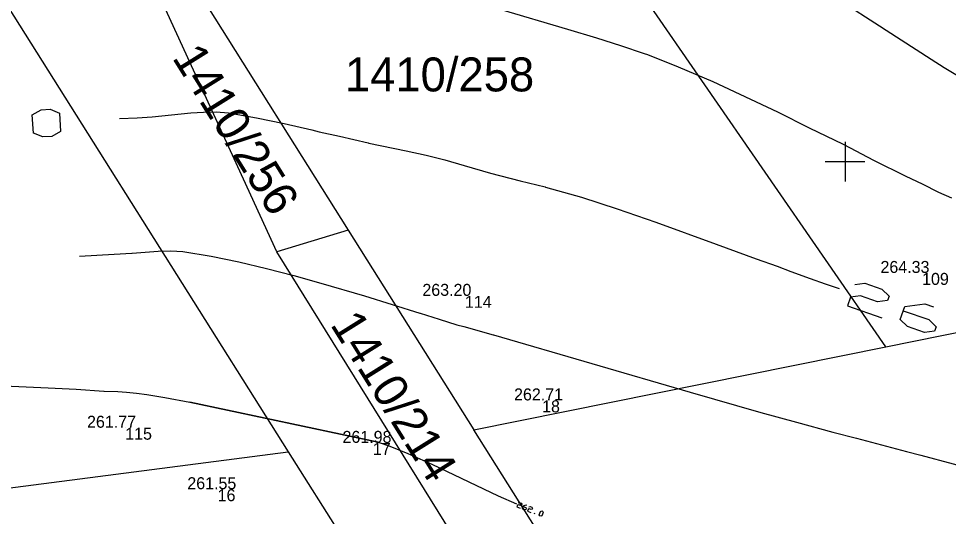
# Model space of a CAD drawing. Extents: x -771260 to -770828, y -1053564 to -1052811.
# Drawn here: x -771091.4 to -771044.82, y -1053317.78 to -1053292.83 of the extents above; entities that cross this region are included whole.
import ezdxf

# ---------------------------------------------------------------- set-up
doc = ezdxf.new("R2010")
doc.units = 0
for name, color, linetype in [('14_8_2023_krizky', 7, 'Continuous'), ('22_4_2022_vrstevnice_interval_po1m', 7, 'Continuous'), ('22_4_2022_zamereny_bod', 7, 'Continuous'), ('22_4_2022_zamereny_bod_cislo', 7, 'Continuous'), ('22_4_2022_zamereny_bod_vyska', 7, 'Continuous'), ('25_3_2019_krizky_JTSK', 7, 'Continuous'), ('25_3_2019_vrstevnice_interval_po_1m', 7, 'Continuous'), ('25_3_2019_zamereny_bod', 7, 'Continuous'), ('25_3_2019_zamereny_bod_cislo', 7, 'Continuous'), ('25_3_2019_zamereny_bod_vyska', 7, 'Continuous'), ('Default', 7, 'Continuous'), ('DKM_Hranice parcel', 7, 'Continuous'), ('DKM_Parcelní čísla', 7, 'Continuous')]:
    doc.layers.add(name, color=color, linetype=linetype)

# ---------------------------------------------------------------- blocks, each defined once
blk = doc.blocks.new('POINT_DISPLAY')
at = {"layer": 'Default'}
blk.add_line((0, 0), (0, 0), dxfattribs=at)
blk = doc.blocks.new('KRIZEK')
at = {"layer": '25_3_2019_krizky_JTSK'}
for p, q in [((0, 10), (0, -10)), ((-10, 0), (10, 0))]:
    blk.add_line(p, q, dxfattribs=at)

msp = doc.modelspace()

# ---------------------------------------------------------------- linework, layer by layer
at = {"layer": '22_4_2022_vrstevnice_interval_po1m'}
for points in [[(-771073.389, -1053314.051), (-771082.816, -1053312.053), (-771073.389, -1053314.051)], [(-771073.389, -1053314.051), (-771072.797, -1053314.255), (-771071.898, -1053314.616), (-771070.701, -1053315.152), (-771067.369, -1053316.747), (-771066.465, -1053317.153)], [(-771072.797, -1053314.255), (-771072.797, -1053314.255)], [(-771071.898, -1053314.616), (-771071.898, -1053314.616)], [(-771070.701, -1053315.152), (-771070.701, -1053315.152)], [(-771067.369, -1053316.747), (-771067.369, -1053316.747)], [(-771066.367, -1053317.098), (-771066.307, -1053317.075), (-771066.218, -1053317.109), (-771066.189, -1053317.167), (-771066.205, -1053317.207), (-771066.265, -1053317.23), (-771066.354, -1053317.196), (-771066.414, -1053317.219), (-771066.445, -1053317.3), (-771066.267, -1053317.369)], [(-771066.132, -1053317.282), (-771065.998, -1053317.334), (-771065.969, -1053317.391), (-771065.985, -1053317.432), (-771066.045, -1053317.455), (-771066.134, -1053317.42), (-771066.163, -1053317.363), (-771066.116, -1053317.242), (-771065.996, -1053317.195), (-771065.951, -1053317.212)], [(-771065.834, -1053317.304), (-771065.774, -1053317.281), (-771065.685, -1053317.316), (-771065.656, -1053317.373), (-771065.671, -1053317.414), (-771065.731, -1053317.437), (-771065.82, -1053317.402), (-771065.881, -1053317.426), (-771065.912, -1053317.506), (-771065.734, -1053317.575)], [(-771065.556, -1053317.644), (-771065.54, -1053317.604)], [(-771065.289, -1053317.747), (-771065.318, -1053317.69), (-771065.256, -1053317.528), (-771065.196, -1053317.505), (-771065.151, -1053317.522), (-771065.122, -1053317.579), (-771065.185, -1053317.741), (-771065.245, -1053317.764), (-771065.289, -1053317.747)]]:
    msp.add_lwpolyline(points, dxfattribs=at)
at = {"layer": '22_4_2022_zamereny_bod'}
for p, q in [((-771065.176, -1053311.963), (-771065.176, -1053311.963)), ((-771073.655, -1053314.092), (-771073.655, -1053314.092)), ((-771081.432, -1053316.413), (-771081.432, -1053316.413))]:
    msp.add_line(p, q, dxfattribs=at)
at = {"layer": '25_3_2019_vrstevnice_interval_po_1m'}
for points in [[(-771050.193, -1053291.95), (-771048.265, -1053293.189), (-771047.941, -1053293.408), (-771045.692, -1053294.867), (-771045.037, -1053295.274), (-771043.5, -1053296.198)], [(-771067.291, -1053292.36), (-771063.905, -1053293.352), (-771062.448, -1053293.796), (-771061.249, -1053294.171), (-771060.062, -1053294.577), (-771059.899, -1053294.632), (-771058.36, -1053295.244), (-771056.63, -1053295.987), (-771053.39, -1053297.507), (-771051.797, -1053298.299), (-771050.089, -1053299.121), (-771050.063, -1053299.133), (-771048.568, -1053299.918), (-771046.947, -1053300.732), (-771046.136, -1053301.11), (-771045.314, -1053301.531), (-771044.661, -1053301.808)], [(-771063.905, -1053293.352), (-771063.905, -1053293.352)], [(-771048.265, -1053293.189), (-771048.265, -1053293.189)], [(-771047.941, -1053293.408), (-771047.941, -1053293.408)], [(-771062.448, -1053293.796), (-771062.448, -1053293.796)], [(-771061.249, -1053294.171), (-771061.249, -1053294.171)], [(-771059.899, -1053294.632), (-771059.899, -1053294.632)], [(-771058.36, -1053295.244), (-771058.36, -1053295.244)], [(-771045.692, -1053294.867), (-771045.692, -1053294.867)], [(-771045.037, -1053295.274), (-771045.037, -1053295.274)], [(-771056.63, -1053295.987), (-771056.63, -1053295.987)], [(-771090.193, -1053298.762), (-771090.66, -1053298.564), (-771090.716, -1053297.658), (-771090.277, -1053297.403), (-771089.824, -1053297.375), (-771089.357, -1053297.574), (-771089.301, -1053298.48), (-771089.74, -1053298.734), (-771090.193, -1053298.762)], [(-771086.347, -1053297.842), (-771085.465, -1053297.797), (-771085.461, -1053297.797), (-771084.713, -1053297.746), (-771082.774, -1053297.561), (-771082.134, -1053297.518), (-771081.505, -1053297.509), (-771080.895, -1053297.558), (-771080.893, -1053297.559), (-771079.49, -1053297.803), (-771078.099, -1053298.092), (-771076.717, -1053298.408), (-771076.338, -1053298.502), (-771075.334, -1053298.721), (-771073.882, -1053299.064), (-771073.86, -1053299.069), (-771071.985, -1053299.459), (-771070.992, -1053299.676), (-771070.043, -1053299.905), (-771069.077, -1053300.193), (-771067.769, -1053300.584), (-771066.27, -1053300.963), (-771065.02, -1053301.268), (-771065.011, -1053301.271), (-771063.196, -1053301.784), (-771061.417, -1053302.361), (-771059.484, -1053303.026), (-771056.45, -1053304.126), (-771054.45, -1053304.871), (-771053.407, -1053305.241), (-771052.715, -1053305.506), (-771051.739, -1053305.857), (-771050.999, -1053306.122), (-771050.3, -1053306.359)], [(-771082.774, -1053297.561), (-771082.774, -1053297.561)], [(-771082.134, -1053297.518), (-771082.134, -1053297.518)], [(-771081.505, -1053297.509), (-771081.505, -1053297.509)], [(-771080.895, -1053297.558), (-771080.895, -1053297.558)], [(-771053.39, -1053297.507), (-771053.39, -1053297.507)], [(-771086.347, -1053297.842), (-771086.347, -1053297.842)], [(-771085.461, -1053297.797), (-771085.461, -1053297.797)], [(-771084.713, -1053297.746), (-771084.713, -1053297.746)], [(-771079.49, -1053297.803), (-771079.49, -1053297.803)], [(-771078.099, -1053298.092), (-771078.099, -1053298.092)], [(-771076.717, -1053298.408), (-771076.717, -1053298.408)], [(-771076.338, -1053298.502), (-771076.338, -1053298.502)], [(-771051.797, -1053298.299), (-771051.797, -1053298.299)], [(-771075.334, -1053298.721), (-771075.334, -1053298.721)], [(-771073.86, -1053299.069), (-771073.86, -1053299.069)], [(-771071.985, -1053299.459), (-771071.985, -1053299.459)], [(-771050.063, -1053299.133), (-771050.063, -1053299.133)], [(-771070.992, -1053299.676), (-771070.992, -1053299.676)], [(-771070.043, -1053299.905), (-771070.043, -1053299.905)], [(-771048.568, -1053299.918), (-771048.568, -1053299.918)], [(-771067.769, -1053300.584), (-771067.769, -1053300.584)], [(-771046.947, -1053300.732), (-771046.947, -1053300.732)], [(-771066.27, -1053300.963), (-771066.27, -1053300.963)], [(-771065.02, -1053301.268), (-771065.02, -1053301.268)], [(-771046.136, -1053301.11), (-771046.136, -1053301.11)], [(-771063.196, -1053301.784), (-771063.196, -1053301.784)], [(-771045.314, -1053301.531), (-771045.314, -1053301.531)], [(-771061.417, -1053302.361), (-771061.417, -1053302.361)], [(-771059.484, -1053303.026), (-771059.484, -1053303.026)], [(-771056.45, -1053304.126), (-771056.45, -1053304.126)], [(-771088.354, -1053304.741), (-771086.607, -1053304.628), (-771085.725, -1053304.578), (-771085.721, -1053304.578), (-771084.416, -1053304.485), (-771083.783, -1053304.461), (-771083.169, -1053304.5), (-771083.167, -1053304.5), (-771081.761, -1053304.735), (-771080.369, -1053305.021), (-771078.991, -1053305.348), (-771077.622, -1053305.702), (-771076.26, -1053306.081), (-771074.066, -1053306.727), (-771071.307, -1053307.584), (-771071.279, -1053307.593), (-771070.335, -1053307.896), (-771069.442, -1053308.172), (-771069.441, -1053308.173), (-771069.099, -1053308.268), (-771067.635, -1053308.676), (-771067.609, -1053308.683), (-771057.761, -1053311.556), (-771054.221, -1053312.564), (-771052.427, -1053313.055), (-771050.605, -1053313.554), (-771049.419, -1053313.86), (-771046.913, -1053314.526), (-771046.201, -1053314.707), (-771042.961, -1053315.581)], [(-771085.721, -1053304.578), (-771085.721, -1053304.578)], [(-771084.416, -1053304.485), (-771084.416, -1053304.485)], [(-771083.783, -1053304.461), (-771083.783, -1053304.461)], [(-771083.169, -1053304.5), (-771083.169, -1053304.5)], [(-771088.354, -1053304.741), (-771088.354, -1053304.741)], [(-771086.607, -1053304.628), (-771086.607, -1053304.628)], [(-771081.761, -1053304.735), (-771081.761, -1053304.735)], [(-771080.369, -1053305.021), (-771080.369, -1053305.021)], [(-771054.45, -1053304.871), (-771054.45, -1053304.871)], [(-771078.991, -1053305.348), (-771078.991, -1053305.348)], [(-771053.407, -1053305.241), (-771053.407, -1053305.241)], [(-771052.715, -1053305.506), (-771052.715, -1053305.506)], [(-771077.622, -1053305.702), (-771077.622, -1053305.702)], [(-771076.26, -1053306.081), (-771076.26, -1053306.081)], [(-771050.999, -1053306.122), (-771050.999, -1053306.122)], [(-771049.509, -1053306.153), (-771049.005, -1053306.086), (-771048.148, -1053306.383), (-771047.793, -1053306.746), (-771047.867, -1053306.961), (-771048.37, -1053307.027), (-771049.228, -1053306.73), (-771049.731, -1053306.796), (-771049.88, -1053307.225), (-771048.164, -1053307.818)], [(-771074.066, -1053306.727), (-771074.066, -1053306.727)], [(-771047.083, -1053307.472), (-771045.797, -1053307.917), (-771045.442, -1053308.28), (-771045.516, -1053308.494), (-771046.019, -1053308.56), (-771046.877, -1053308.264), (-771047.232, -1053307.901), (-771047.009, -1053307.257), (-771046.003, -1053307.125), (-771045.574, -1053307.274)], [(-771071.307, -1053307.584), (-771071.307, -1053307.584)], [(-771070.335, -1053307.896), (-771070.335, -1053307.896)], [(-771069.442, -1053308.172), (-771069.442, -1053308.172)], [(-771067.609, -1053308.683), (-771067.609, -1053308.683)], [(-771100.606, -1053311.279), (-771098.156, -1053311.225), (-771095.444, -1053311.208), (-771092.707, -1053311.234), (-771091.759, -1053311.258), (-771089.927, -1053311.333), (-771088.515, -1053311.406), (-771087.126, -1053311.498), (-771087.108, -1053311.5), (-771086.439, -1053311.524), (-771085.993, -1053311.558), (-771085.494, -1053311.596), (-771085.492, -1053311.596), (-771084.974, -1053311.67), (-771084.079, -1053311.811), (-771082.816, -1053312.053)], [(-771089.927, -1053311.333), (-771089.927, -1053311.333)], [(-771088.515, -1053311.406), (-771088.515, -1053311.406)], [(-771087.108, -1053311.5), (-771087.108, -1053311.5)], [(-771086.439, -1053311.524), (-771086.439, -1053311.524)], [(-771085.494, -1053311.596), (-771085.494, -1053311.596)], [(-771057.761, -1053311.556), (-771057.761, -1053311.556)], [(-771084.974, -1053311.67), (-771084.974, -1053311.67)], [(-771084.079, -1053311.811), (-771084.079, -1053311.811)], [(-771082.816, -1053312.053), (-771082.816, -1053312.053)], [(-771082.56, -1053312.111), (-771082.56, -1053312.111)], [(-771054.221, -1053312.564), (-771054.221, -1053312.564)], [(-771050.605, -1053313.554), (-771050.605, -1053313.554)], [(-771049.419, -1053313.86), (-771049.419, -1053313.86)], [(-771046.913, -1053314.526), (-771046.913, -1053314.526)], [(-771046.201, -1053314.707), (-771046.201, -1053314.707)], [(-771071.527, -1053315.738), (-771071.527, -1053315.738)]]:
    msp.add_lwpolyline(points, dxfattribs=at)
at = {"layer": 'DKM_Hranice parcel'}
for p, q in [((-771047.96, -1053309.28), (-771072.72, -1053273.39)), ((-771089.93, -1053279.48), (-771074.89, -1053303.43)), ((-771078.46, -1053304.52), (-771089.93, -1053279.48)), ((-771074.89, -1053303.43), (-771078.46, -1053304.52)), ((-771074.89, -1053303.43), (-771068.59, -1053313.44)), ((-771047.96, -1053309.28), (-771028.36, -1053305.32)), ((-771068.59, -1053313.44), (-771047.96, -1053309.28)), ((-771060.57, -1053326.21), (-771068.59, -1053313.44)), ((-771104.14, -1053317.95), (-771077.89, -1053314.54)), ((-771077.89, -1053314.54), (-771069.88, -1053327.25))]:
    msp.add_line(p, q, dxfattribs=at)
for points in [[(-771125.28, -1053284.32), (-771118.12, -1053282.56), (-771107.06, -1053280.32), (-771100.29, -1053278.98), (-771077.89, -1053314.54)], [(-771067.24, -1053324.16), (-771069.7, -1053318.64), (-771078.46, -1053304.52)]]:
    msp.add_lwpolyline(points, dxfattribs=at)

# ---------------------------------------------------------------- block references
at = {"layer": '14_8_2023_krizky', "xscale": 0.1, "yscale": 0.10000000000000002}
msp.add_blockref('KRIZEK', (-771050, -1053300), dxfattribs=at)
at = {"layer": '25_3_2019_zamereny_bod', "xscale": 0.1, "yscale": 0.10000000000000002}
for p in [(-771046.139, -1053305.576), (-771069.042, -1053306.724), (-771086.061, -1053313.333)]:
    msp.add_blockref('POINT_DISPLAY', p, dxfattribs=at)

# ---------------------------------------------------------------- texts
at = {"layer": '22_4_2022_zamereny_bod_cislo'}
for s, p in [('18', (-771065.176, -1053312.563)), ('17', (-771073.655, -1053314.692)), ('16', (-771081.432, -1053317.013))]:
    msp.add_text(s, height=0.6, dxfattribs=at).set_placement(p)
at = {"layer": '22_4_2022_zamereny_bod_vyska'}
for s, p in [('262.71 ', (-771066.581, -1053311.963)), ('261.98 ', (-771075.176, -1053314.092)), ('261.55 ', (-771082.95, -1053316.413))]:
    msp.add_text(s, height=0.6, dxfattribs=at).set_placement(p)
at = {"layer": '25_3_2019_zamereny_bod_cislo'}
for s, p in [('109', (-771046.139, -1053306.176)), ('114', (-771069.042, -1053307.324)), ('115', (-771086.061, -1053313.933))]:
    msp.add_text(s, height=0.6, dxfattribs=at).set_placement(p)
at = {"layer": '25_3_2019_zamereny_bod_vyska'}
for s, p in [('264.33 ', (-771048.225, -1053305.576)), ('263.20 ', (-771071.174, -1053306.724)), ('261.77 ', (-771087.974, -1053313.333))]:
    msp.add_text(s, height=0.6, dxfattribs=at).set_placement(p)
at = {"layer": 'DKM_Parcelní čísla'}
for s, p in [('1410/256', (-771083.74, -1053294.791)), ('1410/214', (-771075.82, -1053308.161))]:
    msp.add_text(s, height=1.7, rotation=302, dxfattribs=at).set_placement(p)
msp.add_text('1410/258', height=1.7, dxfattribs=at).set_placement((-771075.055, -1053296.479))

doc.saveas('drawing.dxf')
